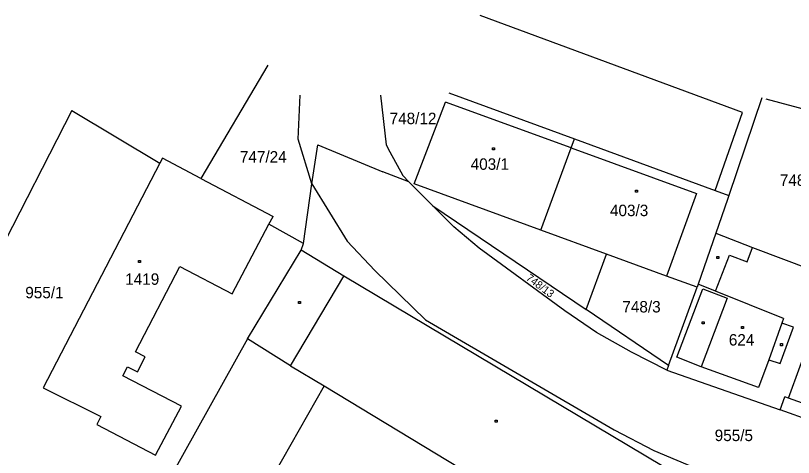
# Model space of a CAD drawing. Extents: x -711879 to -711361, y -1048782 to -1048177.
# Drawn here: x -711762.1 to -711646.6, y -1048283.1 to -1048217.5 of the extents above; entities that cross this region are included whole.
import ezdxf

# ---------------------------------------------------------------- set-up
doc = ezdxf.new("R2010")
doc.units = 0
for name, color, linetype in [('Vrstva 1', 7, 'Continuous'), ('Vrstva 14', 7, 'Continuous'), ('Vrstva 15', 7, 'Continuous'), ('Vrstva 2', 7, 'Continuous'), ('Vrstva 25', 7, 'Continuous'), ('Vrstva 46', 7, 'Continuous')]:
    doc.layers.add(name, color=color, linetype=linetype)

msp = doc.modelspace()

# ---------------------------------------------------------------- linework, layer by layer
at = {"layer": 'Vrstva 1'}
for p, q in [((-711724.63, -1048224.86), (-711734.59, -1048241.68)), ((-711720.12, -1048235.86), (-711719.85, -1048229.33)), ((-711707.91, -1048229.34), (-711707.06, -1048236.7)), ((-711697.74, -1048228.97), (-711679.1, -1048235.81)), ((-711651.23, -1048229.73), (-711656.15, -1048244.2)), ((-711650.65, -1048229.88), (-711633.81, -1048234.32)), ((-711702.89, -1048242.5), (-711698.27, -1048230.34)), ((-711753.75, -1048231.61), (-711773.12, -1048269.27)), ((-711753.75, -1048231.61), (-711740.69, -1048239.41)), ((-711718.12, -1048242.47), (-711720.12, -1048235.86)), ((-711718.12, -1048242.47), (-711717.22, -1048236.72)), ((-711717.22, -1048236.72), (-711707.58, -1048240.7)), ((-711707.06, -1048236.7), (-711706.5, -1048237.74)), ((-711679.59, -1048237.14), (-711679.1, -1048235.81)), ((-711679.1, -1048235.81), (-711658.2, -1048243.48)), ((-711706.5, -1048237.74), (-711704.6, -1048241.27)), ((-711684.07, -1048249.39), (-711679.59, -1048237.14)), ((-711740.3, -1048238.66), (-711740.69, -1048239.41)), ((-711734.59, -1048241.68), (-711740.3, -1048238.66)), ((-711740.69, -1048239.41), (-711758.02, -1048272.79)), ((-711703.68, -1048242.19), (-711707.58, -1048240.7)), ((-711704.6, -1048241.27), (-711703.68, -1048242.19)), ((-711734.59, -1048241.68), (-711723.88, -1048247.36)), ((-711719.34, -1048251.36), (-711718.12, -1048242.47)), ((-711718.12, -1048242.47), (-711712.86, -1048250.99)), ((-711703.68, -1048242.19), (-711700.13, -1048245.75)), ((-711684.07, -1048249.39), (-711702.89, -1048242.5)), ((-711658.2, -1048243.48), (-711656.15, -1048244.2)), ((-711656.37, -1048244.83), (-711658.1, -1048249.84)), ((-711656.15, -1048244.2), (-711656.37, -1048244.83)), ((-711697, -1048248.89), (-711700.13, -1048245.75)), ((-711700.13, -1048245.75), (-711677.37, -1048261.17)), ((-711724.48, -1048248.5), (-711723.88, -1048247.36)), ((-711729.96, -1048258.84), (-711724.48, -1048248.5)), ((-711719.34, -1048251.36), (-711724.48, -1048248.5)), ((-711693.23, -1048252.03), (-711697, -1048248.89)), ((-711674.35, -1048252.94), (-711684.07, -1048249.39)), ((-711658.1, -1048249.84), (-711660.72, -1048257.41)), ((-711658.1, -1048249.84), (-711652.61, -1048251.93)), ((-711719.71, -1048252.32), (-711719.34, -1048251.36)), ((-711712.86, -1048250.99), (-711708.74, -1048255.35)), ((-711727.66, -1048265.49), (-711719.71, -1048252.32)), ((-711680.52, -1048261.36), (-711693.23, -1048252.03)), ((-711677.37, -1048261.17), (-711674.35, -1048252.94)), ((-711665.41, -1048256.2), (-711674.35, -1048252.94)), ((-711652.61, -1048251.93), (-711641.49, -1048256.16)), ((-711744.33, -1048267.45), (-711737.74, -1048254.76)), ((-711737.74, -1048254.76), (-711729.96, -1048258.84)), ((-711708.74, -1048255.35), (-711701.24, -1048262.7)), ((-711660.86, -1048257.82), (-711665.41, -1048256.2)), ((-711660.72, -1048257.41), (-711660.86, -1048257.82)), ((-711665.12, -1048269.47), (-711660.86, -1048257.82)), ((-711665.12, -1048269.47), (-711677.37, -1048261.17)), ((-711675.83, -1048264.56), (-711680.52, -1048261.36)), ((-711701.24, -1048262.7), (-711673.18, -1048279.03)), ((-711670.62, -1048267.47), (-711675.83, -1048264.56)), ((-711727.66, -1048265.49), (-711742.5, -1048292.14)), ((-711721.26, -1048269.53), (-711727.66, -1048265.49)), ((-711647.29, -1048274.32), (-711643.82, -1048264.75)), ((-711742.88, -1048268.2), (-711744.33, -1048267.45)), ((-711665.37, -1048270.17), (-711670.62, -1048267.47)), ((-711744.03, -1048270.41), (-711742.88, -1048268.2)), ((-711746.18, -1048271.02), (-711745.48, -1048269.66)), ((-711745.48, -1048269.66), (-711744.03, -1048270.41)), ((-711721.26, -1048269.53), (-711716.27, -1048272.51)), ((-711665.12, -1048269.47), (-711665.37, -1048270.17)), ((-711665.37, -1048270.17), (-711648.51, -1048276.04)), ((-711737.47, -1048275.53), (-711746.18, -1048271.02)), ((-711716.27, -1048272.51), (-711723.71, -1048285.54)), ((-711758.02, -1048272.79), (-711749.46, -1048277.07)), ((-711648.51, -1048276.04), (-711647.85, -1048274.11)), ((-711647.29, -1048274.32), (-711647.85, -1048274.11)), ((-711741.34, -1048282.78), (-711737.47, -1048275.53)), ((-711635.17, -1048280.88), (-711648.51, -1048276.04)), ((-711749.46, -1048277.07), (-711750.07, -1048278.25)), ((-711750.07, -1048278.25), (-711741.34, -1048282.78)), ((-711673.18, -1048279.03), (-711667.27, -1048282.09)), ((-711667.27, -1048282.09), (-711660.45, -1048284.99))]:
    msp.add_line(p, q, dxfattribs=at)
at = {"layer": 'Vrstva 2'}
for p, q in [((-711654.11, -1048231.9), (-711693.09, -1048217.5)), ((-711679.59, -1048237.14), (-711698.27, -1048230.34)), ((-711658.2, -1048243.48), (-711654.11, -1048231.9)), ((-711679.59, -1048237.14), (-711660.93, -1048243.94)), ((-711660.93, -1048243.94), (-711665.41, -1048256.2)), ((-711713.35, -1048256.2), (-711719.71, -1048252.32)), ((-711653.45, -1048254.1), (-711652.61, -1048251.93)), ((-711658.14, -1048258.43), (-711656.05, -1048253.08)), ((-711656.05, -1048253.08), (-711653.45, -1048254.1)), ((-711721.26, -1048269.53), (-711713.35, -1048256.2)), ((-711660.67, -1048287.56), (-711713.35, -1048256.2)), ((-711658.14, -1048258.43), (-711660.72, -1048257.41)), ((-711663.86, -1048268.24), (-711660, -1048258.08)), ((-711660, -1048258.08), (-711656.41, -1048259.49)), ((-711648.04, -1048262.5), (-711658.14, -1048258.43)), ((-711656.41, -1048259.49), (-711660.26, -1048269.65)), ((-711648.28, -1048263.18), (-711650.19, -1048268.62)), ((-711648.04, -1048262.5), (-711648.28, -1048263.18)), ((-711646.56, -1048263.77), (-711648.28, -1048263.18)), ((-711648.5, -1048269.19), (-711646.56, -1048263.77)), ((-711660.26, -1048269.65), (-711663.86, -1048268.24)), ((-711650.19, -1048268.62), (-711651.75, -1048272.75)), ((-711650.19, -1048268.62), (-711648.5, -1048269.19)), ((-711651.75, -1048272.75), (-711660.26, -1048269.65)), ((-711716.27, -1048272.51), (-711666.19, -1048302.74)), ((-711641.08, -1048276.57), (-711647.29, -1048274.32))]:
    msp.add_line(p, q, dxfattribs=at)
at = {"layer": 'Vrstva 25'}
for p, q in [((-711691.29, -1048237.15), (-711690.99, -1048237.15)), ((-711691.29, -1048237.45), (-711691.29, -1048237.15)), ((-711690.99, -1048237.45), (-711691.29, -1048237.45)), ((-711690.99, -1048237.15), (-711690.99, -1048237.45)), ((-711670.04, -1048243.45), (-711669.74, -1048243.45)), ((-711670.04, -1048243.75), (-711670.04, -1048243.45)), ((-711669.74, -1048243.75), (-711670.04, -1048243.75)), ((-711669.74, -1048243.45), (-711669.74, -1048243.75)), ((-711743.89, -1048253.89), (-711743.59, -1048253.89)), ((-711743.89, -1048254.19), (-711743.89, -1048253.89)), ((-711743.59, -1048254.19), (-711743.89, -1048254.19)), ((-711743.59, -1048253.89), (-711743.59, -1048254.19)), ((-711657.95, -1048253.3), (-711657.65, -1048253.3)), ((-711657.95, -1048253.6), (-711657.95, -1048253.3)), ((-711657.65, -1048253.6), (-711657.95, -1048253.6)), ((-711657.65, -1048253.3), (-711657.65, -1048253.6)), ((-711720.08, -1048259.96), (-711719.78, -1048259.96)), ((-711720.08, -1048260.26), (-711720.08, -1048259.96)), ((-711719.78, -1048259.96), (-711719.78, -1048260.26)), ((-711719.78, -1048260.26), (-711720.08, -1048260.26)), ((-711660.12, -1048262.99), (-711659.82, -1048262.99)), ((-711660.12, -1048263.29), (-711660.12, -1048262.99)), ((-711659.82, -1048263.29), (-711660.12, -1048263.29)), ((-711659.82, -1048262.99), (-711659.82, -1048263.29)), ((-711654.29, -1048263.68), (-711653.99, -1048263.68)), ((-711654.29, -1048263.98), (-711654.29, -1048263.68)), ((-711653.99, -1048263.98), (-711654.29, -1048263.98)), ((-711653.99, -1048263.68), (-711653.99, -1048263.98)), ((-711648.49, -1048266.23), (-711648.19, -1048266.23)), ((-711648.49, -1048266.53), (-711648.49, -1048266.23)), ((-711648.19, -1048266.53), (-711648.49, -1048266.53)), ((-711648.19, -1048266.23), (-711648.19, -1048266.53)), ((-711690.89, -1048277.61), (-711690.59, -1048277.61)), ((-711690.89, -1048277.91), (-711690.89, -1048277.61)), ((-711690.59, -1048277.91), (-711690.89, -1048277.91)), ((-711690.59, -1048277.61), (-711690.59, -1048277.91))]:
    msp.add_line(p, q, dxfattribs=at)
at = {"layer": 'Vrstva 46'}
for p, q in [((-711717.22, -1048236.72), (-711717.22, -1048236.72)), ((-711703.68, -1048242.19), (-711703.68, -1048242.19)), ((-711684.07, -1048249.39), (-711684.07, -1048249.39)), ((-711719.34, -1048251.36), (-711719.34, -1048251.36)), ((-711674.35, -1048252.94), (-711674.35, -1048252.94)), ((-711713.35, -1048256.2), (-711713.35, -1048256.2)), ((-711658.14, -1048258.43), (-711658.14, -1048258.43)), ((-711656.41, -1048259.49), (-711656.41, -1048259.49)), ((-711701.24, -1048262.7), (-711701.24, -1048262.7)), ((-711650.19, -1048268.62), (-711650.19, -1048268.62)), ((-711648.5, -1048269.19), (-711648.5, -1048269.19)), ((-711721.26, -1048269.53), (-711721.26, -1048269.53)), ((-711660.26, -1048269.65), (-711660.26, -1048269.65)), ((-711716.27, -1048272.51), (-711716.27, -1048272.51)), ((-711651.75, -1048272.75), (-711651.75, -1048272.75)), ((-711647.29, -1048274.32), (-711647.29, -1048274.32)), ((-711648.51, -1048276.04), (-711648.51, -1048276.04)), ((-711673.18, -1048279.03), (-711673.18, -1048279.03))]:
    msp.add_line(p, q, dxfattribs=at)

# ---------------------------------------------------------------- texts
at = {"layer": 'Vrstva 14'}
for s, p in [('748/12', (-711706.55, -1048233.63)), ('747/24', (-711728.8, -1048239.33)), ('748/7', (-711648.57, -1048242.8)), ('955/1', (-711760.69, -1048259.49)), ('748/3', (-711671.97, -1048261.6)), ('955/5', (-711658.25, -1048280.7))]:
    msp.add_text(s, height=1.7, dxfattribs=at).set_placement(p)
msp.add_text('748/13', height=1.14, rotation=323.13006, dxfattribs=at).set_placement((-711686.375, -1048256.676))
at = {"layer": 'Vrstva 15'}
for s, p in [('403/1', (-711694.51, -1048240.41)), ('403/3', (-711673.81, -1048247.29)), ('1419', (-711745.84, -1048257.49)), ('624', (-711656.15, -1048266.51))]:
    msp.add_text(s, height=1.7, dxfattribs=at).set_placement(p)

doc.saveas('drawing.dxf')
